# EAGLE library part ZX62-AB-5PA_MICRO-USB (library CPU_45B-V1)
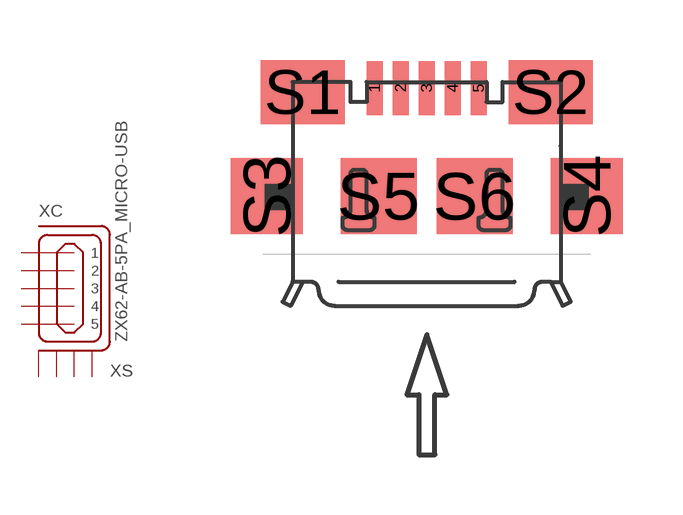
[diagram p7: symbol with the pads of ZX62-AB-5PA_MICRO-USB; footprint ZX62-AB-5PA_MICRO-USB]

Designator prefix X; gates C=MICRO-USB-5P S=SHIELD_4

## ZX62-AB-5PA_MICRO-USB  [ZX62-AB-5PA_MICRO-USB]
1  C:1  pas
2  C:2  pas
3  C:3  pas
4  C:4  pas
5  C:5  pas
S1  S:S1  pas
S2  S:S2  pas
S3  S:S3  pas
S4  S:S4  pas

## Footprint ZX62-AB-5PA_MICRO-USB (pad centres in mm)
smd 0.4 x 1.35: 1 -1.3,1.45; 2 -0.65,1.45; 3 0,1.45; 4 0.65,1.45; 5 1.3,1.45
smd 2.1 x 1.6: S1 -3.1,1.35; S2 3.1,1.35
smd 1.8 x 1.9: S3 -4,-1.25; S4 4,-1.25
smd 1.9 x 1.9: S5 -1.2,-1.25; S6 1.2,-1.25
